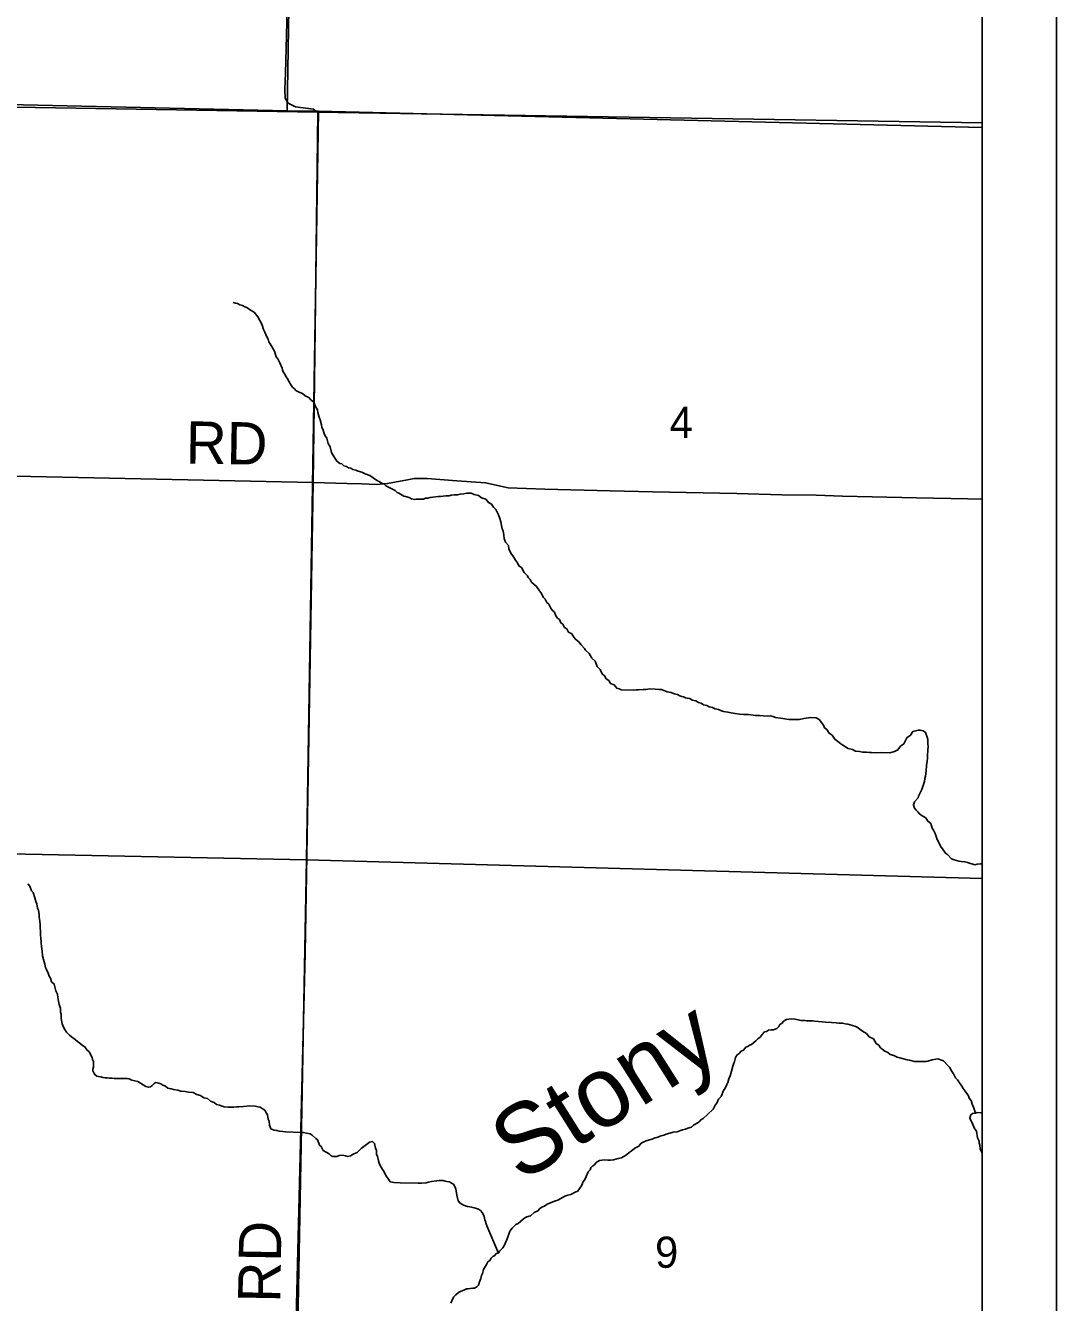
# Model space of a CAD drawing. Extents: x 0 to 34, y 0 to 22.
# Drawn here: x 7.614 to 9, y 16.024 to 17.741 of the extents above; entities that cross this region are included whole.
import ezdxf

# ---------------------------------------------------------------- set-up
doc = ezdxf.new("R2010")
doc.units = 0
for name, color, linetype in [('Default', 7, 'Continuous'), ('GM_X_County_Road', 7, 'Continuous'), ('GM_X_County_Road_Text', 7, 'Continuous'), ('GM_X_Minor_River', 7, 'Continuous'), ('GM_X_Minor_River_Text', 7, 'Continuous'), ('GM_X_Section', 7, 'Continuous'), ('GM_X_Section_Text', 7, 'Continuous'), ('GM_X_Township_Road', 7, 'Continuous'), ('GM_X_Township_Road_Text', 7, 'Continuous'), ('SH_Data', 7, 'Continuous')]:
    doc.layers.add(name, color=color, linetype=linetype)

msp = doc.modelspace()

# ---------------------------------------------------------------- linework, layer by layer
at = {"layer": 'Default'}
for points in [[(8.9, 17.6104), (8.9, 20.9), (6.0871, 20.9), (6.0839, 20.7194), (6.0809, 20.5156), (6.08, 20.4768), (6.0777, 20.3704), (6.0696, 20.0002), (6.0632, 19.7108), (6.0568, 19.5343), (5.9893, 17.6676), (6.9889, 17.643), (7.0308, 17.6406), (8.0065, 17.6245)], [(8.9, 17.6038), (8.9, 18.6218), (7.9821, 18.6451), (7.9657, 17.6264), (8.0077, 17.6258)], [(5.898, 14.1), (8.9, 14.1), (8.9, 17.6104), (8.0065, 17.6245), (7.0308, 17.6406), (6.9889, 17.643), (5.9893, 17.6676), (5.9888, 17.6433), (5.9796, 17.2537), (5.9756, 17.0812), (5.9658, 16.6637), (5.9579, 16.0817), (5.9546, 15.9939), (5.9496, 15.8622), (5.9475, 15.8049), (5.945, 15.7379), (5.9423, 15.6675), (5.9419, 15.65), (5.9251, 14.9951), (5.9162, 14.6505)], [(8.9, 16.5944), (8.9, 17.6038), (8.0077, 17.6258), (7.9916, 16.6192)], [(8.9, 15.5877), (8.9, 16.5944), (7.9916, 16.6192), (7.9729, 15.6119)]]:
    msp.add_lwpolyline(points, close=True, dxfattribs=at)
at = {"layer": 'GM_X_County_Road'}
msp.add_lwpolyline([(7.0254, 17.1457), (7.3255, 17.1409), (8.0006, 17.1268), (8.0462, 17.1251), (8.0661, 17.1246), (8.0859, 17.1239), (8.1006, 17.1251), (8.1276, 17.1304), (8.1363, 17.1318), (8.1541, 17.1318), (8.1939, 17.129), (8.2324, 17.1263), (8.2628, 17.1193), (8.312, 17.1178), (8.4, 17.1155), (8.4569, 17.1141), (8.5703, 17.1117), (8.6307, 17.1102), (8.6767, 17.1096), (8.7121, 17.1081), (8.8119, 17.1058), (8.8808, 17.1047), (8.9, 17.1042)], dxfattribs=at)
at = {"layer": 'GM_X_Minor_River'}
for points in [[(8.03, 17.159), (8.0271, 17.164), (8.0253, 17.167), (8.0235, 17.1747), (8.021, 17.1789), (8.0189, 17.1862), (8.0166, 17.1893), (8.0156, 17.1924), (8.0138, 17.1981), (8.0123, 17.2004), (8.0117, 17.2042), (8.0099, 17.2107), (8.0085, 17.2146), (8.0071, 17.2207), (8.0064, 17.2245), (8.0039, 17.2287), (8.0013, 17.2345), (7.998, 17.2372), (7.9947, 17.2411), (7.9898, 17.2431), (7.9864, 17.2463), (7.9826, 17.2475), (7.98, 17.2491), (7.9774, 17.2503), (7.9755, 17.2526), (7.9733, 17.2542), (7.9714, 17.2565), (7.9685, 17.2619), (7.9656, 17.2669), (7.9637, 17.2692), (7.9627, 17.2723), (7.9605, 17.2754), (7.9594, 17.2781), (7.9591, 17.2804), (7.9558, 17.2877), (7.9533, 17.293), (7.951, 17.2954), (7.9486, 17.303), (7.9427, 17.3131), (7.9412, 17.3158), (7.9402, 17.3192), (7.938, 17.3234), (7.9358, 17.3288), (7.934, 17.3323), (7.9319, 17.338), (7.9312, 17.3403), (7.929, 17.3445), (7.926, 17.3492), (7.9212, 17.3554), (7.9164, 17.3582), (7.9115, 17.3617), (7.9089, 17.3629), (7.9055, 17.3645), (7.9021, 17.3657), (7.8991, 17.3673), (7.8964, 17.3678), (7.893, 17.3686)], [(8.3611, 16.9084), (8.3578, 16.9126), (8.3533, 16.9158), (8.3511, 16.9185), (8.3482, 16.9231), (8.344, 16.9255), (8.3415, 16.9298), (8.3385, 16.9317), (8.3363, 16.936), (8.3337, 16.9379), (8.3319, 16.9422), (8.3293, 16.9441), (8.3271, 16.9472), (8.3253, 16.9522), (8.3219, 16.9549), (8.3201, 16.9576), (8.3175, 16.963), (8.3149, 16.9654), (8.3127, 16.9696), (8.3101, 16.9719), (8.3069, 16.9785), (8.305, 16.9808), (8.301, 16.9866), (8.2943, 16.9928), (8.2924, 16.9963), (8.2898, 16.9987), (8.2887, 17.001), (8.2843, 17.0056), (8.2806, 17.0122), (8.2773, 17.0145), (8.2755, 17.0184), (8.2725, 17.0223), (8.2699, 17.0265), (8.2666, 17.0315), (8.2637, 17.0373), (8.2631, 17.0419), (8.2594, 17.0465), (8.2576, 17.0515), (8.2569, 17.0557), (8.2559, 17.0614), (8.2548, 17.0641), (8.2538, 17.0687), (8.2528, 17.0736), (8.2514, 17.0782), (8.25, 17.0832), (8.2463, 17.0905), (8.243, 17.0933), (8.2404, 17.0975), (8.2363, 17.0995), (8.2326, 17.1042), (8.2269, 17.1062), (8.2228, 17.1093), (8.2171, 17.1106), (8.213, 17.1122), (8.2073, 17.1124), (8.2031, 17.1113), (8.1981, 17.1111), (8.1947, 17.11), (8.1905, 17.1101), (8.1863, 17.1095), (8.1836, 17.1088), (8.1791, 17.1089), (8.1718, 17.1079), (8.1688, 17.1076), (8.1581, 17.1064), (8.155, 17.1057), (8.1516, 17.1054), (8.1489, 17.1043), (8.1447, 17.1041), (8.139, 17.1042), (8.1367, 17.1039), (8.133, 17.1047), (8.1296, 17.1063), (8.1247, 17.1076), (8.1224, 17.1084), (8.1201, 17.1096), (8.1156, 17.1124), (8.1134, 17.1132), (8.1108, 17.1159), (8.1081, 17.1171), (8.101, 17.1207), (8.0984, 17.1223), (8.0958, 17.1247), (8.0927, 17.1255), (8.0894, 17.1278), (8.0871, 17.129), (8.0811, 17.133), (8.0766, 17.1361), (8.0706, 17.1382), (8.0661, 17.1406), (8.0612, 17.1418), (8.0578, 17.1434), (8.054, 17.1443), (8.0514, 17.1459), (8.048, 17.1463), (8.0454, 17.1479), (8.042, 17.1492), (8.039, 17.1515), (8.0363, 17.1523), (8.0326, 17.1551), (8.03, 17.159)], [(8.8209, 16.7929), (8.8163, 16.7937), (8.8141, 16.7938), (8.8106, 16.7927), (8.8068, 16.7917), (8.8036, 16.7868), (8.799, 16.7832), (8.795, 16.7753), (8.7904, 16.772), (8.7868, 16.7671), (8.7822, 16.765), (8.7761, 16.7632), (8.7654, 16.7635), (8.7586, 16.7633), (8.7514, 16.7634), (8.7483, 16.7635), (8.7445, 16.764), (8.7392, 16.7641), (8.7354, 16.765), (8.7297, 16.7655), (8.7256, 16.7675), (8.7199, 16.7688), (8.7128, 16.7735), (8.7102, 16.7751), (8.708, 16.7771), (8.702, 16.7814), (8.6983, 16.7868), (8.6942, 16.7896), (8.6912, 16.7946), (8.6883, 16.7969), (8.6868, 16.8004), (8.6839, 16.8039), (8.6809, 16.8081), (8.6768, 16.8101), (8.6699, 16.8107), (8.6665, 16.8104), (8.6604, 16.8094), (8.6547, 16.808), (8.6459, 16.8079), (8.6402, 16.808), (8.6323, 16.8093), (8.6224, 16.8107), (8.6186, 16.812), (8.6156, 16.8128), (8.6114, 16.8125), (8.6008, 16.8132), (8.5955, 16.8133), (8.586, 16.8147), (8.5792, 16.8148), (8.5738, 16.8153), (8.5678, 16.8159), (8.5628, 16.8168), (8.5583, 16.818), (8.5523, 16.8189), (8.5496, 16.8197), (8.5458, 16.8214), (8.5413, 16.8222), (8.5375, 16.8242), (8.533, 16.8251), (8.53, 16.8267), (8.5255, 16.8279), (8.5225, 16.8299), (8.5187, 16.8308), (8.5149, 16.8331), (8.5104, 16.834), (8.507, 16.836), (8.5036, 16.8365), (8.5013, 16.8373), (8.4987, 16.8385), (8.4961, 16.8389), (8.4938, 16.8397), (8.4904, 16.8417), (8.4859, 16.8426), (8.4821, 16.8442), (8.4768, 16.8451), (8.4689, 16.8483), (8.4655, 16.8484), (8.4605, 16.8489), (8.4533, 16.8491), (8.448, 16.8485), (8.4445, 16.8482), (8.4381, 16.848), (8.435, 16.8477), (8.4316, 16.8474), (8.4149, 16.8478), (8.4122, 16.849), (8.4088, 16.8502), (8.4051, 16.8545), (8.4006, 16.8565), (8.3981, 16.8604), (8.3947, 16.8627), (8.3925, 16.8666), (8.3891, 16.8693), (8.3866, 16.8751), (8.3825, 16.879), (8.3796, 16.8863), (8.3752, 16.8902), (8.3719, 16.8967), (8.3667, 16.901), (8.3656, 16.9033), (8.3611, 16.9084)], [(8.9, 16.6146), (8.8981, 16.6139), (8.8932, 16.6133), (8.8901, 16.6126), (8.8875, 16.6134), (8.8833, 16.6147), (8.8803, 16.6155), (8.8769, 16.6167), (8.872, 16.6172), (8.8689, 16.6177), (8.8655, 16.6182), (8.8625, 16.6194), (8.8587, 16.6206), (8.8535, 16.6264), (8.8509, 16.6284), (8.8469, 16.6342), (8.845, 16.6365), (8.8417, 16.6423), (8.8392, 16.6481), (8.8367, 16.6546), (8.8345, 16.6592), (8.8331, 16.6619), (8.8309, 16.668), (8.8272, 16.6712), (8.8243, 16.6758), (8.8205, 16.6782), (8.8183, 16.6794), (8.8153, 16.6817), (8.8134, 16.684), (8.8112, 16.686), (8.809, 16.6887), (8.8076, 16.6933), (8.8092, 16.6974), (8.8139, 16.7026), (8.8147, 16.7049), (8.8167, 16.7094), (8.8187, 16.7128), (8.8203, 16.718), (8.8224, 16.7248), (8.8232, 16.7286), (8.8237, 16.7316), (8.8246, 16.7385), (8.8251, 16.7464), (8.826, 16.7513), (8.8265, 16.7559), (8.8266, 16.7601), (8.8271, 16.7665), (8.8273, 16.7722), (8.8269, 16.7749), (8.8271, 16.7809), (8.826, 16.7844), (8.8239, 16.7905), (8.8209, 16.7929)], [(7.6379, 16.4853), (7.6369, 16.4903), (7.6363, 16.4963), (7.6353, 16.5028), (7.635, 16.5074), (7.6347, 16.5101), (7.6344, 16.5131), (7.6342, 16.5192), (7.6339, 16.5226), (7.6336, 16.5287), (7.6337, 16.5317), (7.633, 16.5367), (7.6327, 16.539), (7.6324, 16.5428), (7.6321, 16.5455), (7.6311, 16.5516), (7.63, 16.5542), (7.629, 16.5603), (7.6276, 16.5634), (7.6265, 16.5684), (7.624, 16.5753), (7.6218, 16.5776), (7.6197, 16.5841), (7.6171, 16.5869)], [(7.9413, 16.2677), (7.9402, 16.2704), (7.9392, 16.2765), (7.9374, 16.2792), (7.9356, 16.2826), (7.9333, 16.2842), (7.9292, 16.2866), (7.9265, 16.287), (7.9231, 16.2879), (7.9152, 16.2885), (7.9114, 16.2882), (7.9068, 16.2875), (7.9007, 16.2873), (7.8976, 16.287), (7.8938, 16.2867), (7.8862, 16.2869), (7.8809, 16.2874), (7.8783, 16.2879), (7.8745, 16.2895), (7.8707, 16.2903), (7.8677, 16.2931), (7.8628, 16.2947), (7.8587, 16.2982), (7.8534, 16.2995), (7.8493, 16.3023), (7.844, 16.3039), (7.8391, 16.3063), (7.8331, 16.3068), (7.8285, 16.3077), (7.8228, 16.3082), (7.8187, 16.3095), (7.813, 16.3104), (7.8096, 16.3116), (7.8051, 16.3125), (7.8021, 16.3148), (7.7983, 16.3161), (7.7957, 16.318), (7.793, 16.3188), (7.7885, 16.3197), (7.7862, 16.3183), (7.7842, 16.316), (7.7819, 16.3142), (7.7792, 16.3135), (7.7758, 16.3147), (7.765, 16.3214), (7.757, 16.3232), (7.7532, 16.3248), (7.7506, 16.3252), (7.7449, 16.3254), (7.7358, 16.3252), (7.7331, 16.3253), (7.7305, 16.3257), (7.7263, 16.3258), (7.7236, 16.3263), (7.721, 16.3263), (7.7179, 16.3268), (7.7153, 16.3276), (7.7119, 16.3281), (7.7096, 16.3285), (7.707, 16.3305), (7.7059, 16.3328), (7.7044, 16.3355), (7.7045, 16.3378), (7.7053, 16.3404), (7.7054, 16.3449), (7.7051, 16.348), (7.704, 16.3507), (7.7033, 16.3534), (7.6993, 16.3611), (7.6963, 16.3638), (7.6938, 16.368), (7.6904, 16.3696), (7.687, 16.3728), (7.6837, 16.3751), (7.6807, 16.3775), (7.6758, 16.3814), (7.6729, 16.3837), (7.6691, 16.3876), (7.6669, 16.3911), (7.6651, 16.3942), (7.6633, 16.3988), (7.6623, 16.4038), (7.662, 16.4061), (7.6617, 16.4118), (7.661, 16.4144), (7.6608, 16.4198), (7.66, 16.4221), (7.6593, 16.4247), (7.6583, 16.4293), (7.6573, 16.4343), (7.657, 16.4385), (7.6548, 16.4431), (7.6524, 16.4523), (7.649, 16.4554), (7.6476, 16.4604), (7.6458, 16.4627), (7.6444, 16.4669), (7.6422, 16.4719), (7.6407, 16.4746), (7.6397, 16.4792), (7.6379, 16.4853)], [(8.8911, 16.2787), (8.8883, 16.2867), (8.8868, 16.2906), (8.8851, 16.2959), (8.8828, 16.299), (8.8818, 16.3021), (8.8774, 16.3083), (8.8744, 16.3118), (8.8726, 16.3148), (8.8696, 16.3195), (8.8671, 16.3237), (8.8641, 16.3261), (8.8615, 16.3315), (8.859, 16.3357), (8.8564, 16.3403), (8.8534, 16.3431), (8.8482, 16.3489), (8.8456, 16.3501), (8.8407, 16.3517), (8.838, 16.3514), (8.8327, 16.3504), (8.827, 16.3486), (8.8247, 16.3483), (8.8209, 16.348), (8.8091, 16.3483), (8.8026, 16.35), (8.7992, 16.3505), (8.7894, 16.353), (8.786, 16.3538), (8.7815, 16.3562), (8.7762, 16.3575), (8.7732, 16.3602), (8.7691, 16.3622), (8.7635, 16.3666), (8.7613, 16.37), (8.7575, 16.3724), (8.7539, 16.3786), (8.7482, 16.3814), (8.7445, 16.386), (8.7393, 16.3888), (8.7322, 16.3943), (8.7288, 16.3955), (8.7193, 16.3984), (8.7159, 16.3989), (8.7121, 16.3997), (8.7076, 16.3999), (8.7038, 16.4003), (8.6977, 16.4005), (8.6894, 16.4011), (8.6852, 16.4016), (8.6749, 16.4022), (8.6719, 16.4026), (8.6643, 16.4028), (8.6613, 16.4033), (8.6563, 16.4034), (8.6529, 16.4043), (8.6484, 16.4051), (8.6431, 16.4056), (8.637, 16.4047), (8.6331, 16.4025), (8.6311, 16.3999), (8.6281, 16.3977), (8.6265, 16.395), (8.6241, 16.3924), (8.6195, 16.3907), (8.6169, 16.3907), (8.6127, 16.3901), (8.61, 16.3886), (8.6073, 16.3879), (8.6042, 16.3846), (8.6014, 16.3808), (8.5987, 16.3786), (8.596, 16.376), (8.5898, 16.3709), (8.5875, 16.3702), (8.5852, 16.3683), (8.5825, 16.3673), (8.5794, 16.3635), (8.5759, 16.3621), (8.5732, 16.3588), (8.5708, 16.3569), (8.5685, 16.3535), (8.5672, 16.3483), (8.5656, 16.3445), (8.5648, 16.3419), (8.5631, 16.3351), (8.5611, 16.3287), (8.5594, 16.3249), (8.5582, 16.32), (8.5566, 16.3174), (8.5546, 16.3121), (8.5522, 16.3091), (8.5494, 16.3012), (8.5455, 16.2975), (8.5435, 16.2919), (8.5411, 16.2893), (8.5383, 16.284), (8.5306, 16.277), (8.5251, 16.2714), (8.522, 16.2696), (8.5197, 16.267)], [(8.9, 16.279), (8.8987, 16.2792), (8.8934, 16.2794), (8.8911, 16.2787), (8.8873, 16.2784), (8.885, 16.2765), (8.8837, 16.2724), (8.8844, 16.2697), (8.8866, 16.2655), (8.8899, 16.2582), (8.8925, 16.2543), (8.8938, 16.2456), (8.896, 16.2409), (8.8959, 16.2387), (8.897, 16.2356), (8.8976, 16.2306), (8.8987, 16.2276), (8.9, 16.2254)], [(8.2498, 16.0906), (8.2339, 16.1274), (8.2332, 16.1301), (8.2321, 16.1328), (8.2314, 16.1351), (8.2304, 16.1397), (8.2293, 16.1428), (8.2279, 16.1451), (8.2256, 16.1478), (8.2227, 16.1498), (8.22, 16.1506), (8.217, 16.1514), (8.2136, 16.1523), (8.2113, 16.1527), (8.2083, 16.1532), (8.2056, 16.154), (8.2026, 16.1548), (8.1981, 16.1576), (8.1955, 16.1607), (8.1938, 16.1683), (8.1928, 16.1741), (8.1925, 16.1763), (8.1914, 16.179), (8.1892, 16.1833), (8.1866, 16.1845), (8.1839, 16.1864), (8.1805, 16.1869), (8.1783, 16.1873), (8.1756, 16.1882), (8.1703, 16.1883), (8.1665, 16.1876), (8.1596, 16.1867), (8.1558, 16.186), (8.1524, 16.1849), (8.1463, 16.1847), (8.1417, 16.1844), (8.1174, 16.185), (8.109, 16.1856), (8.1067, 16.1861), (8.1041, 16.1865), (8.1008, 16.1912), (8.0989, 16.1939), (8.0957, 16.2008), (8.0938, 16.2031), (8.0902, 16.2093), (8.0895, 16.2116), (8.0884, 16.2146), (8.087, 16.2208), (8.0859, 16.2231), (8.0857, 16.2284), (8.0846, 16.2318), (8.0832, 16.2379), (8.0806, 16.2407), (8.0764, 16.2396), (8.0722, 16.2367), (8.0652, 16.2312), (8.0629, 16.229), (8.0597, 16.2256), (8.0551, 16.2238), (8.0509, 16.2213), (8.0471, 16.2206), (8.044, 16.2211), (8.0418, 16.2219), (8.0388, 16.2223), (8.0357, 16.2216), (8.0326, 16.2206), (8.03, 16.2203), (8.0269, 16.2203), (8.0247, 16.2215), (8.0221, 16.2239), (8.0142, 16.2286), (8.0113, 16.2337), (8.009, 16.2356), (8.0083, 16.2383), (8.0065, 16.2429), (8.0043, 16.2445), (7.9994, 16.2491), (7.9964, 16.2507), (7.9915, 16.252), (7.9877, 16.2525), (7.9847, 16.2529), (7.9634, 16.2535), (7.96, 16.2539), (7.9551, 16.2544), (7.9517, 16.2553), (7.9483, 16.2557), (7.946, 16.2565), (7.9437, 16.2577), (7.9427, 16.2604), (7.942, 16.2627), (7.9413, 16.2677)], [(8.5197, 16.267), (8.5162, 16.2648), (8.512, 16.2626), (8.5093, 16.26), (8.5043, 16.2586), (8.5012, 16.2572), (8.497, 16.2562), (8.4943, 16.2555), (8.4901, 16.2537), (8.4848, 16.2531), (8.4802, 16.2517), (8.4752, 16.2506), (8.4721, 16.2492), (8.4683, 16.2481), (8.4629, 16.246), (8.4606, 16.2453), (8.456, 16.2439), (8.4484, 16.2414), (8.4445, 16.2396), (8.4418, 16.2382), (8.4387, 16.2344), (8.4329, 16.2315), (8.4283, 16.2275), (8.4256, 16.226), (8.4221, 16.2227), (8.4151, 16.2187), (8.4109, 16.2177), (8.4075, 16.217), (8.4044, 16.2159), (8.4006, 16.2156), (8.3968, 16.2157), (8.3919, 16.2159), (8.3858, 16.2152), (8.3812, 16.2123), (8.3788, 16.209), (8.3765, 16.2079), (8.3741, 16.2053), (8.3729, 16.2023), (8.3702, 16.1997), (8.3678, 16.1933), (8.3654, 16.1888), (8.3634, 16.1858), (8.3622, 16.1828), (8.3606, 16.1798), (8.3587, 16.1775), (8.3563, 16.1738), (8.3536, 16.1727), (8.3471, 16.1691), (8.3429, 16.1684), (8.339, 16.167), (8.3367, 16.1656), (8.3294, 16.1619), (8.3263, 16.1609), (8.3183, 16.1577), (8.3152, 16.1562), (8.3117, 16.1536), (8.309, 16.1529), (8.3056, 16.1507), (8.3028, 16.1474), (8.2978, 16.1452), (8.2928, 16.1408), (8.2878, 16.1394), (8.2851, 16.138), (8.2828, 16.1361), (8.2793, 16.1332), (8.2762, 16.1302), (8.2731, 16.1288), (8.2681, 16.1239), (8.2649, 16.1198), (8.2609, 16.1085), (8.2597, 16.1059), (8.2588, 16.1033), (8.258, 16.101), (8.2557, 16.0977), (8.251, 16.0932), (8.2498, 16.0906), (8.2467, 16.0899), (8.2448, 16.0873), (8.2421, 16.0858), (8.2398, 16.0836), (8.2382, 16.0806), (8.2355, 16.0788), (8.2335, 16.0754), (8.2311, 16.0709), (8.2295, 16.0687), (8.2283, 16.063), (8.227, 16.0604), (8.2262, 16.0566), (8.225, 16.054), (8.2242, 16.0517), (8.223, 16.0476), (8.2206, 16.045), (8.2175, 16.0435), (8.2152, 16.0432), (8.2118, 16.0429), (8.2091, 16.0426), (8.2069, 16.0423), (8.203, 16.0408), (8.1996, 16.0394), (8.1961, 16.0376), (8.1926, 16.0346)], [(8.1926, 16.0346), (8.1895, 16.0313), (8.1871, 16.0264), (8.1855, 16.023)]]:
    msp.add_lwpolyline(points, dxfattribs=at)
at = {"layer": 'GM_X_Section'}
for points in [[(7.008, 18.6577), (7.9821, 18.6451), (7.9657, 17.6264), (7.0384, 17.6474), (7.0009, 17.6487)], [(7.0384, 17.6474), (7.9657, 17.6264), (8.0077, 17.6258), (7.9916, 16.6192), (7.0136, 16.6391)], [(7.0136, 16.6391), (7.9916, 16.6192), (7.9729, 15.6119), (6.9929, 15.633)]]:
    msp.add_lwpolyline(points, close=True, dxfattribs=at)
at = {"layer": 'GM_X_Township_Road'}
for points in [[(7.9669, 17.6364), (7.963, 17.6433), (7.9627, 17.6556), (7.9635, 17.677), (7.9647, 17.7272), (7.9666, 17.8059), (7.9676, 18.0527), (7.9705, 18.2198), (7.9708, 18.2258)], [(8.0043, 17.626), (8.0011, 17.6287), (7.9767, 17.6318), (7.9669, 17.6364)], [(7.9603, 15.1054), (7.9633, 15.279), (7.9669, 15.4627), (7.97, 15.632), (7.9749, 15.8672), (7.978, 16.0209), (7.9897, 16.4938), (8.0006, 17.1268), (8.0031, 17.3329), (8.0067, 17.6239), (8.0043, 17.626)]]:
    msp.add_lwpolyline(points, dxfattribs=at)
at = {"layer": 'SH_Data'}
for p, q in [((9, 21), (9, 14)), ((8.9, 20.9), (8.9, 14.1))]:
    msp.add_line(p, q, dxfattribs=at)

# ---------------------------------------------------------------- texts
at = {"layer": 'GM_X_County_Road_Text'}
msp.add_text('RD', height=0.05682, rotation=359.0128, dxfattribs=at).set_placement((7.829, 17.1522))
at = {"layer": 'GM_X_Minor_River_Text'}
msp.add_text('Stony', height=0.09469, rotation=32.2714, dxfattribs=at).set_placement((8.2797, 16.1842))
at = {"layer": 'GM_X_Section_Text'}
for s, p in [('4', (8.4798, 17.1865)), ('9', (8.4603, 16.0708))]:
    msp.add_text(s, height=0.0419, rotation=0, dxfattribs=at).set_placement(p)
at = {"layer": 'GM_X_Township_Road_Text'}
msp.add_text('RD', height=0.05682, rotation=89.0123, dxfattribs=at).set_placement((7.9563, 16.0236))

doc.saveas('drawing.dxf')
